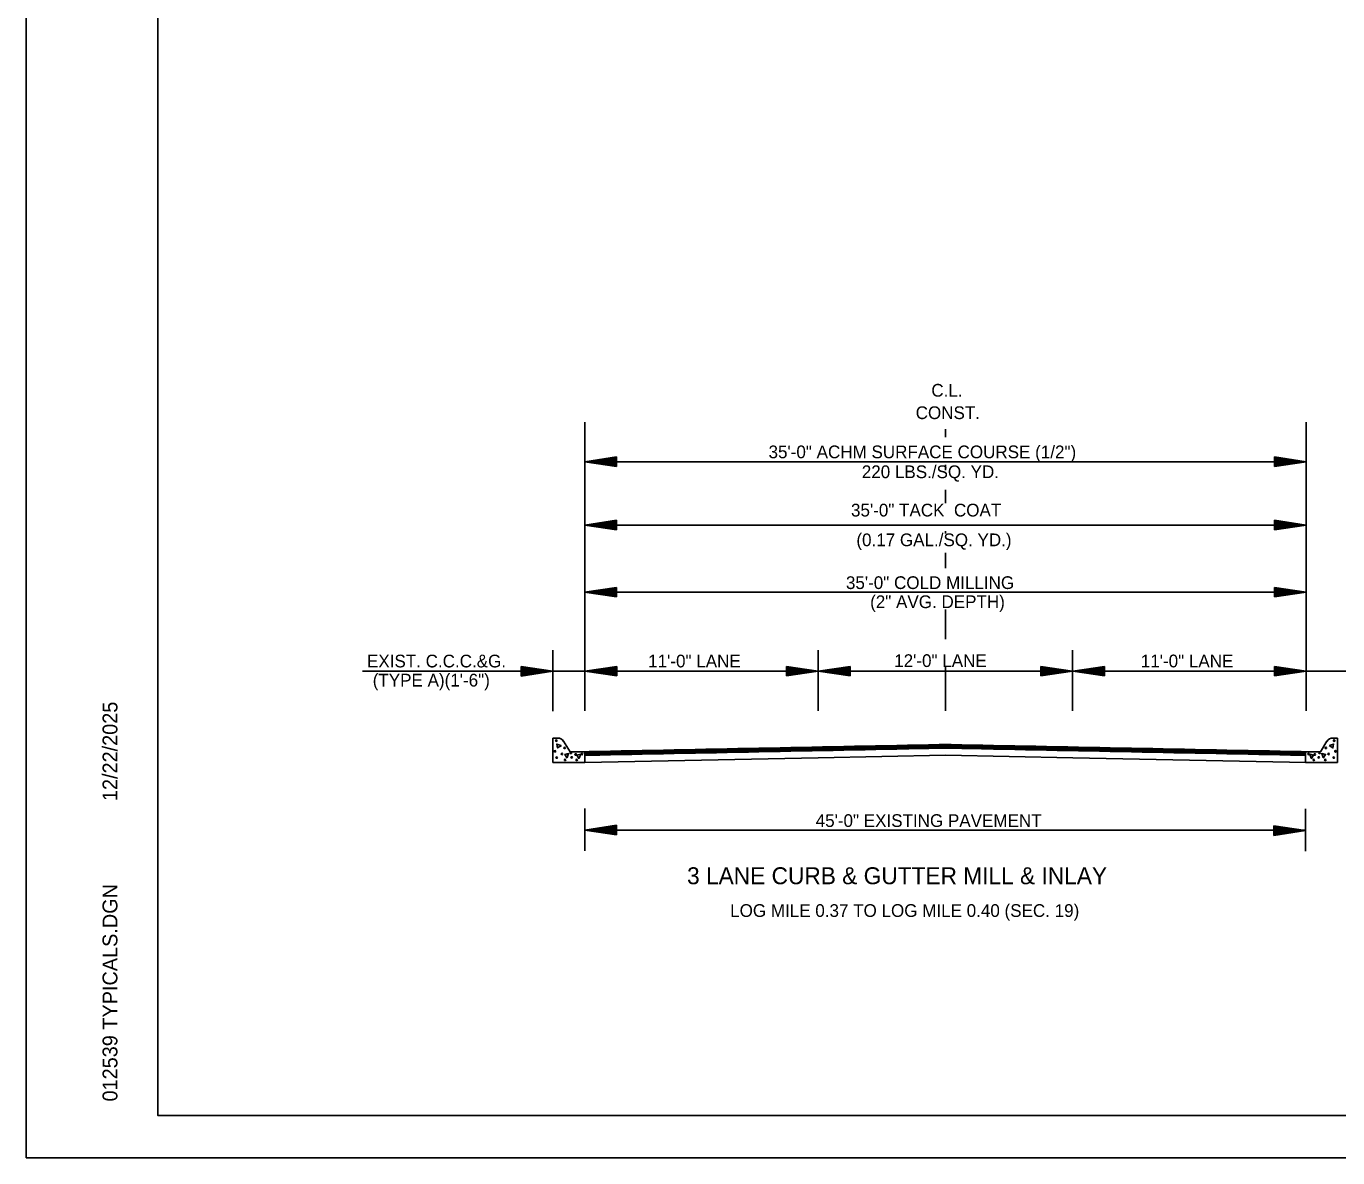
# Model space of a CAD drawing. Extents: x 2263886 to 2266026, y -3122850 to -3121850.
# Drawn here: x 2265859 to 2265920.8, y -3122443.8 to -3122390.5 of the extents above; entities that cross this region are included whole.
import ezdxf

# ---------------------------------------------------------------- set-up
doc = ezdxf.new("R2010")
doc.units = 0
for name, color, linetype in [('_CIVIL_CONSTRUCTION', 7, 'Continuous'), ('R_Border Prem', 7, 'Continuous'), ('R_Draft', 7, 'Continuous')]:
    doc.layers.add(name, color=color, linetype=linetype)

msp = doc.modelspace()

# ---------------------------------------------------------------- linework, layer by layer
at = {"layer": '_CIVIL_CONSTRUCTION'}
msp.add_line((2265859.035, -3122443.817), (2266025.702, -3122443.817), dxfattribs=at)
for points in [[(2265859.032, -3122337.151), (2266025.702, -3122337.151), (2266025.702, -3122443.82), (2265859.032, -3122443.82)], [(2265982.196, -3122339.098), (2265982.196, -3122344.038), (2266000.062, -3122344.038), (2266000.062, -3122345.498), (2266011.661, -3122345.498), (2266011.661, -3122357.664), (2266023.326, -3122357.664), (2266023.326, -3122441.828), (2265865.236, -3122441.828), (2265865.236, -3122339.098)]]:
    msp.add_lwpolyline(points, close=True, dxfattribs=at)
at = {"layer": 'R_Border Prem'}
for p, q in [((2265885.36, -3122420.886), (2265885.36, -3122409.142)), ((2265919.36, -3122422.752), (2265919.36, -3122409.142)), ((2265902.358, -3122409.854), (2265902.358, -3122409.474)), ((2265886.86, -3122410.786), (2265885.36, -3122411.011)), ((2265885.36, -3122411.01), (2265919.36, -3122411.01)), ((2265886.86, -3122411.236), (2265885.36, -3122411.011)), ((2265886.86, -3122410.824), (2265885.61, -3122411.011)), ((2265886.86, -3122411.199), (2265885.61, -3122411.011)), ((2265886.86, -3122410.862), (2265885.868, -3122411.011)), ((2265886.86, -3122411.161), (2265885.868, -3122411.011)), ((2265886.86, -3122410.9), (2265886.118, -3122411.011)), ((2265886.86, -3122411.123), (2265886.118, -3122411.011)), ((2265886.86, -3122410.938), (2265886.372, -3122411.011)), ((2265886.86, -3122411.084), (2265886.372, -3122411.011)), ((2265886.86, -3122410.976), (2265886.623, -3122411.011)), ((2265886.86, -3122411.047), (2265886.623, -3122411.011)), ((2265886.86, -3122411.236), (2265886.86, -3122410.786)), ((2265902.358, -3122411.405), (2265902.358, -3122411.159)), ((2265917.86, -3122410.785), (2265919.36, -3122411.01)), ((2265917.86, -3122410.785), (2265917.86, -3122411.235)), ((2265917.86, -3122410.823), (2265919.109, -3122411.01)), ((2265917.86, -3122410.861), (2265918.851, -3122411.01)), ((2265917.86, -3122410.898), (2265918.601, -3122411.01)), ((2265917.86, -3122410.937), (2265918.347, -3122411.01)), ((2265917.86, -3122410.975), (2265918.097, -3122411.01)), ((2265917.86, -3122411.235), (2265919.36, -3122411.01)), ((2265917.86, -3122411.084), (2265918.347, -3122411.01)), ((2265917.86, -3122411.159), (2265918.851, -3122411.01)), ((2265917.86, -3122411.198), (2265919.109, -3122411.01)), ((2265917.86, -3122411.122), (2265918.601, -3122411.01)), ((2265917.86, -3122411.045), (2265918.097, -3122411.01)), ((2265902.358, -3122412.965), (2265902.358, -3122412.331)), ((2265886.86, -3122413.774), (2265885.36, -3122413.999)), ((2265886.86, -3122414.224), (2265885.36, -3122413.999)), ((2265885.36, -3122413.999), (2265919.36, -3122413.999)), ((2265886.86, -3122413.811), (2265885.61, -3122413.999)), ((2265886.86, -3122414.186), (2265885.61, -3122413.999)), ((2265886.86, -3122413.85), (2265885.868, -3122413.999)), ((2265886.86, -3122414.148), (2265885.868, -3122413.999)), ((2265886.86, -3122413.887), (2265886.118, -3122413.999)), ((2265886.86, -3122414.111), (2265886.118, -3122413.999)), ((2265886.86, -3122413.925), (2265886.372, -3122413.999)), ((2265886.86, -3122414.072), (2265886.372, -3122413.999)), ((2265886.86, -3122413.964), (2265886.623, -3122413.999)), ((2265886.86, -3122414.034), (2265886.623, -3122413.999)), ((2265886.86, -3122414.224), (2265886.86, -3122413.774)), ((2265902.358, -3122414.394), (2265902.358, -3122414.281)), ((2265917.86, -3122413.774), (2265919.36, -3122413.999)), ((2265917.86, -3122413.774), (2265917.86, -3122414.224)), ((2265917.86, -3122413.811), (2265919.109, -3122413.999)), ((2265917.86, -3122413.85), (2265918.851, -3122413.999)), ((2265917.86, -3122413.887), (2265918.601, -3122413.999)), ((2265917.86, -3122413.926), (2265918.347, -3122413.999)), ((2265917.86, -3122413.964), (2265918.097, -3122413.999)), ((2265917.86, -3122414.224), (2265919.36, -3122413.999)), ((2265917.86, -3122414.072), (2265918.347, -3122413.999)), ((2265917.86, -3122414.148), (2265918.851, -3122413.999)), ((2265917.86, -3122414.186), (2265919.109, -3122413.999)), ((2265917.86, -3122414.111), (2265918.601, -3122413.999)), ((2265917.86, -3122414.034), (2265918.097, -3122413.999)), ((2265902.358, -3122416.026), (2265902.358, -3122415.303)), ((2265886.852, -3122416.934), (2265885.352, -3122417.159)), ((2265886.852, -3122417.384), (2265885.352, -3122417.159)), ((2265885.36, -3122417.159), (2265919.36, -3122417.159)), ((2265886.852, -3122416.972), (2265885.602, -3122417.159)), ((2265886.852, -3122417.347), (2265885.602, -3122417.159)), ((2265886.852, -3122417.01), (2265885.86, -3122417.159)), ((2265886.852, -3122417.308), (2265885.86, -3122417.159)), ((2265886.852, -3122417.047), (2265886.11, -3122417.159)), ((2265886.852, -3122417.271), (2265886.11, -3122417.159)), ((2265886.852, -3122417.086), (2265886.364, -3122417.159)), ((2265886.852, -3122417.232), (2265886.364, -3122417.159)), ((2265886.852, -3122417.124), (2265886.615, -3122417.159)), ((2265886.852, -3122417.194), (2265886.615, -3122417.159)), ((2265886.852, -3122417.384), (2265886.852, -3122416.934)), ((2265917.86, -3122416.934), (2265919.36, -3122417.159)), ((2265917.86, -3122416.934), (2265917.86, -3122417.384)), ((2265917.86, -3122416.972), (2265919.109, -3122417.159)), ((2265917.86, -3122417.01), (2265918.851, -3122417.159)), ((2265917.86, -3122417.047), (2265918.601, -3122417.159)), ((2265917.86, -3122417.086), (2265918.347, -3122417.159)), ((2265917.86, -3122417.124), (2265918.097, -3122417.159)), ((2265917.86, -3122417.384), (2265919.36, -3122417.159)), ((2265917.86, -3122417.233), (2265918.347, -3122417.159)), ((2265917.86, -3122417.308), (2265918.851, -3122417.159)), ((2265917.86, -3122417.347), (2265919.109, -3122417.159)), ((2265917.86, -3122417.271), (2265918.601, -3122417.159)), ((2265917.86, -3122417.194), (2265918.097, -3122417.159)), ((2265902.358, -3122419.376), (2265902.358, -3122417.977)), ((2265883.86, -3122422.769), (2265883.86, -3122419.897)), ((2265885.36, -3122422.752), (2265885.36, -3122419.897)), ((2265896.36, -3122422.752), (2265896.36, -3122419.897)), ((2265908.352, -3122422.752), (2265908.352, -3122419.897)), ((2265885.36, -3122420.886), (2265874.882, -3122420.886)), ((2265882.359, -3122420.662), (2265883.859, -3122420.887)), ((2265882.359, -3122420.662), (2265882.359, -3122421.112)), ((2265882.359, -3122420.699), (2265883.608, -3122420.887)), ((2265882.359, -3122420.737), (2265883.35, -3122420.887)), ((2265882.359, -3122420.775), (2265883.101, -3122420.887)), ((2265882.359, -3122420.814), (2265882.846, -3122420.887)), ((2265882.359, -3122420.851), (2265882.596, -3122420.887)), ((2265882.359, -3122421.112), (2265883.859, -3122420.887)), ((2265882.359, -3122420.96), (2265882.846, -3122420.887)), ((2265882.359, -3122421.036), (2265883.35, -3122420.887)), ((2265882.359, -3122421.074), (2265883.608, -3122420.887)), ((2265882.359, -3122420.998), (2265883.101, -3122420.887)), ((2265882.359, -3122420.922), (2265882.596, -3122420.887)), ((2265885.36, -3122420.886), (2265896.36, -3122420.886)), ((2265886.867, -3122420.661), (2265885.367, -3122420.886)), ((2265886.867, -3122421.111), (2265885.367, -3122420.886)), ((2265886.867, -3122420.699), (2265885.617, -3122420.886)), ((2265886.867, -3122421.074), (2265885.617, -3122420.886)), ((2265886.867, -3122420.737), (2265885.875, -3122420.886)), ((2265886.867, -3122421.035), (2265885.875, -3122420.886)), ((2265886.867, -3122420.774), (2265886.125, -3122420.886)), ((2265886.867, -3122420.998), (2265886.125, -3122420.886)), ((2265886.867, -3122420.813), (2265886.379, -3122420.886)), ((2265886.867, -3122420.959), (2265886.379, -3122420.886)), ((2265886.867, -3122420.851), (2265886.63, -3122420.886)), ((2265886.867, -3122420.921), (2265886.63, -3122420.886)), ((2265886.867, -3122421.111), (2265886.867, -3122420.661)), ((2265894.86, -3122420.661), (2265896.36, -3122420.886)), ((2265894.86, -3122420.661), (2265894.86, -3122421.111)), ((2265894.86, -3122420.699), (2265896.109, -3122420.886)), ((2265894.86, -3122420.737), (2265895.851, -3122420.886)), ((2265894.86, -3122420.774), (2265895.601, -3122420.886)), ((2265894.86, -3122420.813), (2265895.347, -3122420.886)), ((2265894.86, -3122420.851), (2265895.097, -3122420.886)), ((2265894.86, -3122421.111), (2265896.36, -3122420.886)), ((2265894.86, -3122420.96), (2265895.347, -3122420.886)), ((2265894.86, -3122421.035), (2265895.851, -3122420.886)), ((2265894.86, -3122421.074), (2265896.109, -3122420.886)), ((2265894.86, -3122420.998), (2265895.601, -3122420.886)), ((2265894.86, -3122420.921), (2265895.097, -3122420.886)), ((2265896.352, -3122420.886), (2265908.352, -3122420.886)), ((2265897.86, -3122420.661), (2265896.36, -3122420.886)), ((2265897.86, -3122421.111), (2265896.36, -3122420.886)), ((2265897.86, -3122420.699), (2265896.61, -3122420.886)), ((2265897.86, -3122421.074), (2265896.61, -3122420.886)), ((2265897.86, -3122420.737), (2265896.868, -3122420.886)), ((2265897.86, -3122421.035), (2265896.868, -3122420.886)), ((2265897.86, -3122420.774), (2265897.118, -3122420.886)), ((2265897.86, -3122420.998), (2265897.118, -3122420.886)), ((2265897.86, -3122420.813), (2265897.372, -3122420.886)), ((2265897.86, -3122420.959), (2265897.372, -3122420.886)), ((2265897.86, -3122420.851), (2265897.623, -3122420.886)), ((2265897.86, -3122420.921), (2265897.623, -3122420.886)), ((2265897.86, -3122421.111), (2265897.86, -3122420.661)), ((2265902.358, -3122422.752), (2265902.358, -3122420.675)), ((2265906.852, -3122420.661), (2265908.352, -3122420.886)), ((2265906.852, -3122420.661), (2265906.852, -3122421.111)), ((2265906.852, -3122420.699), (2265908.102, -3122420.886)), ((2265906.852, -3122420.737), (2265907.844, -3122420.886)), ((2265906.852, -3122420.774), (2265907.594, -3122420.886)), ((2265906.852, -3122420.813), (2265907.34, -3122420.886)), ((2265906.852, -3122420.851), (2265907.089, -3122420.886)), ((2265906.852, -3122421.111), (2265908.352, -3122420.886)), ((2265906.852, -3122420.96), (2265907.34, -3122420.886)), ((2265906.852, -3122421.035), (2265907.844, -3122420.886)), ((2265906.852, -3122421.074), (2265908.102, -3122420.886)), ((2265906.852, -3122420.998), (2265907.594, -3122420.886)), ((2265906.852, -3122420.921), (2265907.089, -3122420.886)), ((2265909.86, -3122420.661), (2265908.36, -3122420.886)), ((2265909.86, -3122421.111), (2265908.36, -3122420.886)), ((2265908.36, -3122420.886), (2265919.367, -3122420.886)), ((2265909.86, -3122420.699), (2265908.61, -3122420.886)), ((2265909.86, -3122421.074), (2265908.61, -3122420.886)), ((2265909.86, -3122420.737), (2265908.868, -3122420.886)), ((2265909.86, -3122421.035), (2265908.868, -3122420.886)), ((2265909.86, -3122420.774), (2265909.118, -3122420.886)), ((2265909.86, -3122420.998), (2265909.118, -3122420.886)), ((2265909.86, -3122420.813), (2265909.372, -3122420.886)), ((2265909.86, -3122420.959), (2265909.372, -3122420.886)), ((2265909.86, -3122420.851), (2265909.623, -3122420.886)), ((2265909.86, -3122420.921), (2265909.623, -3122420.886)), ((2265909.86, -3122421.111), (2265909.86, -3122420.661)), ((2265917.86, -3122420.661), (2265919.36, -3122420.886)), ((2265917.86, -3122420.661), (2265917.86, -3122421.111)), ((2265917.86, -3122420.699), (2265919.109, -3122420.886)), ((2265917.86, -3122420.737), (2265918.851, -3122420.886)), ((2265917.86, -3122420.774), (2265918.601, -3122420.886)), ((2265917.86, -3122420.813), (2265918.347, -3122420.886)), ((2265917.86, -3122420.851), (2265918.097, -3122420.886)), ((2265917.86, -3122421.111), (2265919.36, -3122420.886)), ((2265917.86, -3122420.96), (2265918.347, -3122420.886)), ((2265917.86, -3122421.035), (2265918.851, -3122420.886)), ((2265917.86, -3122421.074), (2265919.109, -3122420.886)), ((2265917.86, -3122420.998), (2265918.601, -3122420.886)), ((2265917.86, -3122420.921), (2265918.097, -3122420.886)), ((2265919.36, -3122420.886), (2265929.817, -3122420.886)), ((2265884.076, -3122424.04), (2265883.86, -3122424.044)), ((2265883.86, -3122424.044), (2265883.86, -3122425.189)), ((2265920.616, -3122424.04), (2265920.833, -3122424.044)), ((2265920.833, -3122424.044), (2265920.833, -3122425.189)), ((2265884.358, -3122424.19), (2265884.667, -3122424.68)), ((2265884.667, -3122424.68), (2265885.36, -3122424.68)), ((2265885.35, -3122424.85), (2265896.347, -3122424.63)), ((2265885.36, -3122424.68), (2265896.344, -3122424.46)), ((2265885.36, -3122424.679), (2265885.36, -3122425.189)), ((2265885.36, -3122424.68), (2265885.36, -3122425.029)), ((2265885.36, -3122424.68), (2265885.36, -3122425.029)), ((2265893.569, -3122424.686), (2265885.36, -3122424.686)), ((2265885.374, -3122424.689), (2265885.36, -3122424.689)), ((2265893.069, -3122424.696), (2265885.36, -3122424.696)), ((2265892.569, -3122424.706), (2265885.36, -3122424.706)), ((2265892.069, -3122424.716), (2265885.36, -3122424.716)), ((2265891.569, -3122424.726), (2265885.36, -3122424.726)), ((2265891.069, -3122424.736), (2265885.36, -3122424.736)), ((2265890.569, -3122424.746), (2265885.36, -3122424.746)), ((2265890.069, -3122424.756), (2265885.36, -3122424.756)), ((2265889.57, -3122424.766), (2265885.36, -3122424.766)), ((2265889.07, -3122424.776), (2265885.36, -3122424.776)), ((2265888.57, -3122424.786), (2265885.36, -3122424.786)), ((2265894.069, -3122424.676), (2265885.569, -3122424.676)), ((2265894.569, -3122424.666), (2265886.069, -3122424.666)), ((2265895.068, -3122424.656), (2265886.568, -3122424.656)), ((2265895.568, -3122424.646), (2265887.068, -3122424.646)), ((2265896.068, -3122424.636), (2265887.568, -3122424.636)), ((2265896.568, -3122424.626), (2265888.068, -3122424.626)), ((2265897.068, -3122424.616), (2265888.568, -3122424.616)), ((2265897.568, -3122424.606), (2265889.068, -3122424.606)), ((2265898.068, -3122424.596), (2265889.568, -3122424.596)), ((2265898.568, -3122424.586), (2265890.068, -3122424.586)), ((2265899.068, -3122424.576), (2265890.568, -3122424.576)), ((2265899.567, -3122424.566), (2265891.068, -3122424.566)), ((2265900.067, -3122424.556), (2265891.567, -3122424.556)), ((2265900.567, -3122424.546), (2265892.067, -3122424.546)), ((2265901.067, -3122424.536), (2265892.567, -3122424.536)), ((2265901.567, -3122424.526), (2265893.067, -3122424.526)), ((2265902.067, -3122424.516), (2265893.567, -3122424.516)), ((2265910.626, -3122424.506), (2265894.067, -3122424.506)), ((2265910.126, -3122424.496), (2265894.567, -3122424.496)), ((2265909.626, -3122424.486), (2265895.067, -3122424.486)), ((2265909.126, -3122424.476), (2265895.567, -3122424.476)), ((2265908.626, -3122424.466), (2265896.067, -3122424.466)), ((2265896.344, -3122424.46), (2265902.343, -3122424.34)), ((2265896.347, -3122424.63), (2265902.346, -3122424.51)), ((2265908.126, -3122424.456), (2265896.566, -3122424.456)), ((2265907.625, -3122424.446), (2265897.066, -3122424.446)), ((2265907.125, -3122424.436), (2265897.566, -3122424.436)), ((2265906.624, -3122424.426), (2265898.066, -3122424.426)), ((2265906.124, -3122424.416), (2265898.566, -3122424.416)), ((2265905.624, -3122424.406), (2265899.066, -3122424.406)), ((2265905.123, -3122424.396), (2265899.566, -3122424.396)), ((2265904.623, -3122424.386), (2265900.066, -3122424.386)), ((2265904.122, -3122424.376), (2265900.566, -3122424.376)), ((2265903.622, -3122424.366), (2265901.065, -3122424.366)), ((2265903.121, -3122424.356), (2265901.565, -3122424.356)), ((2265902.621, -3122424.346), (2265902.065, -3122424.346)), ((2265902.346, -3122424.51), (2265908.345, -3122424.63)), ((2265902.35, -3122424.34), (2265908.348, -3122424.46)), ((2265911.125, -3122424.516), (2265902.626, -3122424.516)), ((2265911.625, -3122424.526), (2265903.125, -3122424.526)), ((2265912.125, -3122424.536), (2265903.625, -3122424.536)), ((2265912.625, -3122424.546), (2265904.125, -3122424.546)), ((2265913.125, -3122424.556), (2265904.625, -3122424.556)), ((2265913.625, -3122424.566), (2265905.125, -3122424.566)), ((2265914.125, -3122424.576), (2265905.625, -3122424.576)), ((2265914.625, -3122424.586), (2265906.125, -3122424.586)), ((2265915.125, -3122424.596), (2265906.625, -3122424.596)), ((2265915.625, -3122424.606), (2265907.125, -3122424.606)), ((2265916.124, -3122424.616), (2265907.624, -3122424.616)), ((2265916.624, -3122424.626), (2265908.124, -3122424.626)), ((2265908.345, -3122424.63), (2265919.343, -3122424.85)), ((2265908.348, -3122424.46), (2265919.333, -3122424.68)), ((2265917.124, -3122424.636), (2265908.624, -3122424.636)), ((2265917.624, -3122424.646), (2265909.124, -3122424.646)), ((2265918.124, -3122424.656), (2265909.624, -3122424.656)), ((2265918.624, -3122424.666), (2265910.124, -3122424.666)), ((2265919.124, -3122424.676), (2265910.624, -3122424.676)), ((2265919.333, -3122424.686), (2265911.124, -3122424.686)), ((2265919.333, -3122424.696), (2265911.624, -3122424.696)), ((2265919.333, -3122424.706), (2265912.124, -3122424.706)), ((2265919.333, -3122424.716), (2265912.623, -3122424.716)), ((2265919.333, -3122424.726), (2265913.123, -3122424.726)), ((2265919.333, -3122424.736), (2265913.623, -3122424.736)), ((2265919.333, -3122424.746), (2265914.123, -3122424.746)), ((2265919.333, -3122424.756), (2265914.623, -3122424.756)), ((2265919.333, -3122424.766), (2265915.123, -3122424.766)), ((2265919.333, -3122424.776), (2265915.623, -3122424.776)), ((2265919.333, -3122424.786), (2265916.123, -3122424.786)), ((2265919.333, -3122424.685), (2265919.122, -3122424.685)), ((2265919.333, -3122424.679), (2265919.333, -3122425.189)), ((2265920.025, -3122424.68), (2265919.333, -3122424.68)), ((2265919.333, -3122424.68), (2265919.333, -3122425.029)), ((2265919.333, -3122424.68), (2265919.333, -3122425.029)), ((2265920.334, -3122424.19), (2265920.025, -3122424.68)), ((2265885.36, -3122425.189), (2265883.86, -3122425.189)), ((2265888.07, -3122424.796), (2265885.36, -3122424.796)), ((2265887.57, -3122424.806), (2265885.36, -3122424.806)), ((2265887.07, -3122424.816), (2265885.36, -3122424.816)), ((2265886.57, -3122424.826), (2265885.36, -3122424.826)), ((2265886.07, -3122424.836), (2265885.36, -3122424.836)), ((2265885.57, -3122424.846), (2265885.36, -3122424.846)), ((2265885.36, -3122425.189), (2265896.357, -3122424.969)), ((2265896.357, -3122424.969), (2265902.356, -3122424.849)), ((2265902.356, -3122424.849), (2265908.355, -3122424.969)), ((2265908.355, -3122424.969), (2265919.353, -3122425.189)), ((2265919.333, -3122424.796), (2265916.623, -3122424.796)), ((2265919.333, -3122424.806), (2265917.123, -3122424.806)), ((2265919.333, -3122424.816), (2265917.622, -3122424.816)), ((2265919.333, -3122424.826), (2265918.122, -3122424.826)), ((2265919.333, -3122424.836), (2265918.622, -3122424.836)), ((2265919.333, -3122425.189), (2265920.833, -3122425.189)), ((2265885.36, -3122427.35), (2265885.36, -3122429.35)), ((2265919.333, -3122427.375), (2265919.333, -3122429.375)), ((2265886.86, -3122428.15), (2265885.36, -3122428.375)), ((2265885.36, -3122428.375), (2265919.333, -3122428.375)), ((2265886.86, -3122428.6), (2265885.36, -3122428.375)), ((2265886.86, -3122428.187), (2265885.61, -3122428.375)), ((2265886.86, -3122428.562), (2265885.61, -3122428.375)), ((2265886.86, -3122428.226), (2265885.868, -3122428.375)), ((2265886.86, -3122428.524), (2265885.868, -3122428.375)), ((2265886.86, -3122428.263), (2265886.118, -3122428.375)), ((2265886.86, -3122428.487), (2265886.118, -3122428.375)), ((2265886.86, -3122428.301), (2265886.372, -3122428.375)), ((2265886.86, -3122428.448), (2265886.372, -3122428.375)), ((2265886.86, -3122428.34), (2265886.623, -3122428.375)), ((2265886.86, -3122428.41), (2265886.623, -3122428.375)), ((2265886.86, -3122428.6), (2265886.86, -3122428.15)), ((2265917.833, -3122428.175), (2265919.333, -3122428.4)), ((2265917.833, -3122428.625), (2265917.833, -3122428.175)), ((2265917.833, -3122428.212), (2265919.082, -3122428.4)), ((2265917.833, -3122428.251), (2265918.824, -3122428.4)), ((2265917.833, -3122428.288), (2265918.575, -3122428.4)), ((2265917.833, -3122428.326), (2265918.32, -3122428.4)), ((2265917.833, -3122428.365), (2265918.07, -3122428.4)), ((2265917.833, -3122428.625), (2265919.333, -3122428.4)), ((2265917.833, -3122428.473), (2265918.32, -3122428.4)), ((2265917.833, -3122428.549), (2265918.824, -3122428.4)), ((2265917.833, -3122428.587), (2265919.082, -3122428.4)), ((2265917.833, -3122428.512), (2265918.575, -3122428.4)), ((2265917.833, -3122428.435), (2265918.07, -3122428.4))]:
    msp.add_line(p, q, dxfattribs=at)
for points in [[(2265884.254, -3122424.386), (2265884.078, -3122424.5), (2265884.04, -3122424.322), (2265884.23, -3122424.386)], [(2265884.535, -3122424.984), (2265884.421, -3122424.805), (2265884.598, -3122424.769), (2265884.535, -3122424.958)], [(2265920.158, -3122424.984), (2265920.271, -3122424.805), (2265920.095, -3122424.769), (2265920.158, -3122424.958)], [(2265920.439, -3122424.386), (2265920.615, -3122424.5), (2265920.653, -3122424.322), (2265920.462, -3122424.386)], [(2265885.101, -3122425.016), (2265884.987, -3122424.838), (2265885.165, -3122424.801), (2265885.101, -3122424.99)], [(2265919.592, -3122425.016), (2265919.705, -3122424.838), (2265919.528, -3122424.801), (2265919.592, -3122424.99)]]:
    msp.add_lwpolyline(points, dxfattribs=at)
for centre in [(2265884.015, -3122424.158), (2265920.677, -3122424.158), (2265883.953, -3122424.66), (2265884.281, -3122424.787), (2265884.408, -3122424.501), (2265884.701, -3122424.734), (2265884.931, -3122424.812), (2265885.225, -3122424.794), (2265919.468, -3122424.794), (2265919.761, -3122424.812), (2265919.992, -3122424.734), (2265920.284, -3122424.501), (2265920.411, -3122424.787), (2265920.74, -3122424.66), (2265884.034, -3122424.958), (2265884.433, -3122425.065), (2265884.741, -3122424.951), (2265884.977, -3122425.065), (2265919.715, -3122425.065), (2265919.951, -3122424.951), (2265920.259, -3122425.065), (2265920.658, -3122424.958)]:
    msp.add_circle(centre, 0.0339, dxfattribs=at)
for centre, start, end in [((2265884.082, -3122424.366), 32.27564, 91.11964), ((2265920.611, -3122424.366), 88.88036, 147.72436)]:
    msp.add_arc(centre, 0.326, start, end, dxfattribs=at)
at = {"layer": 'R_Draft'}
for p, q in [((2265865.236, -3122441.828), (2265865.236, -3122339.098)), ((2265865.236, -3122441.828), (2265865.236, -3122441.828)), ((2266023.326, -3122441.828), (2265865.236, -3122441.828))]:
    msp.add_line(p, q, dxfattribs=at)

# ---------------------------------------------------------------- texts
at = {"layer": 'R_Border Prem'}
for s, height, p in [('C.L.', 0.6, (2265901.691, -3122407.945)), ('CONST.', 0.6, (2265900.954, -3122409.002)), ('35\'-0" ACHM SURFACE COURSE (1/2")', 0.6, (2265894.019, -3122410.848)), ('220 LBS./SQ. YD. ', 0.6, (2265898.414, -3122411.786)), ('35\'-0" TACK  COAT', 0.6, (2265897.905, -3122413.593)), ('(0.17 GAL./SQ. YD.)', 0.6, (2265898.159, -3122414.994)), ('35\'-0" COLD MILLING', 0.6, (2265897.666, -3122417.012)), ('(2" AVG. DEPTH)', 0.6, (2265898.807, -3122417.912)), ('EXIST. C.C.C.&G.', 0.6, (2265875.094, -3122420.707)), ('11\'-0" LANE', 0.6, (2265888.346, -3122420.706)), ('12\'-0" LANE', 0.6, (2265899.941, -3122420.688)), ('11\'-0" LANE', 0.6, (2265911.563, -3122420.704)), ('(TYPE A)(1\'-6")', 0.6, (2265875.364, -3122421.607)), ('45\'-0" EXISTING PAVEMENT', 0.6, (2265896.24, -3122428.227)), ('3 LANE CURB & GUTTER MILL & INLAY', 0.8, (2265890.178, -3122430.926)), ('LOG MILE 0.37 TO LOG MILE 0.40 (SEC. 19)', 0.6, (2265892.21, -3122432.467))]:
    msp.add_text(s, height=height, dxfattribs=at).set_placement(p)
at = {"layer": 'R_Draft'}
for s, p in [('12/22/2025', (2265863.331, -3122427.007)), ('012539 TYPICALS.DGN', (2265863.331, -3122441.166))]:
    msp.add_text(s, height=0.7, rotation=90, dxfattribs=at).set_placement(p)

doc.saveas('drawing.dxf')
